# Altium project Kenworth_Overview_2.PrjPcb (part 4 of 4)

## Sheet Rectifier.SchDoc: <Document>
size Letter; Engineer: <Engineer>; Organization: UPEL; Address1: USU Power Electronics Lab; Address2: USTAR Building 620, RM 118; Address3: 1600 N 620 E; Address4: North Logan, UT 84341; DocumentNumber: 13; Revision: v1; SheetNumber: 13; SheetTotal: 16
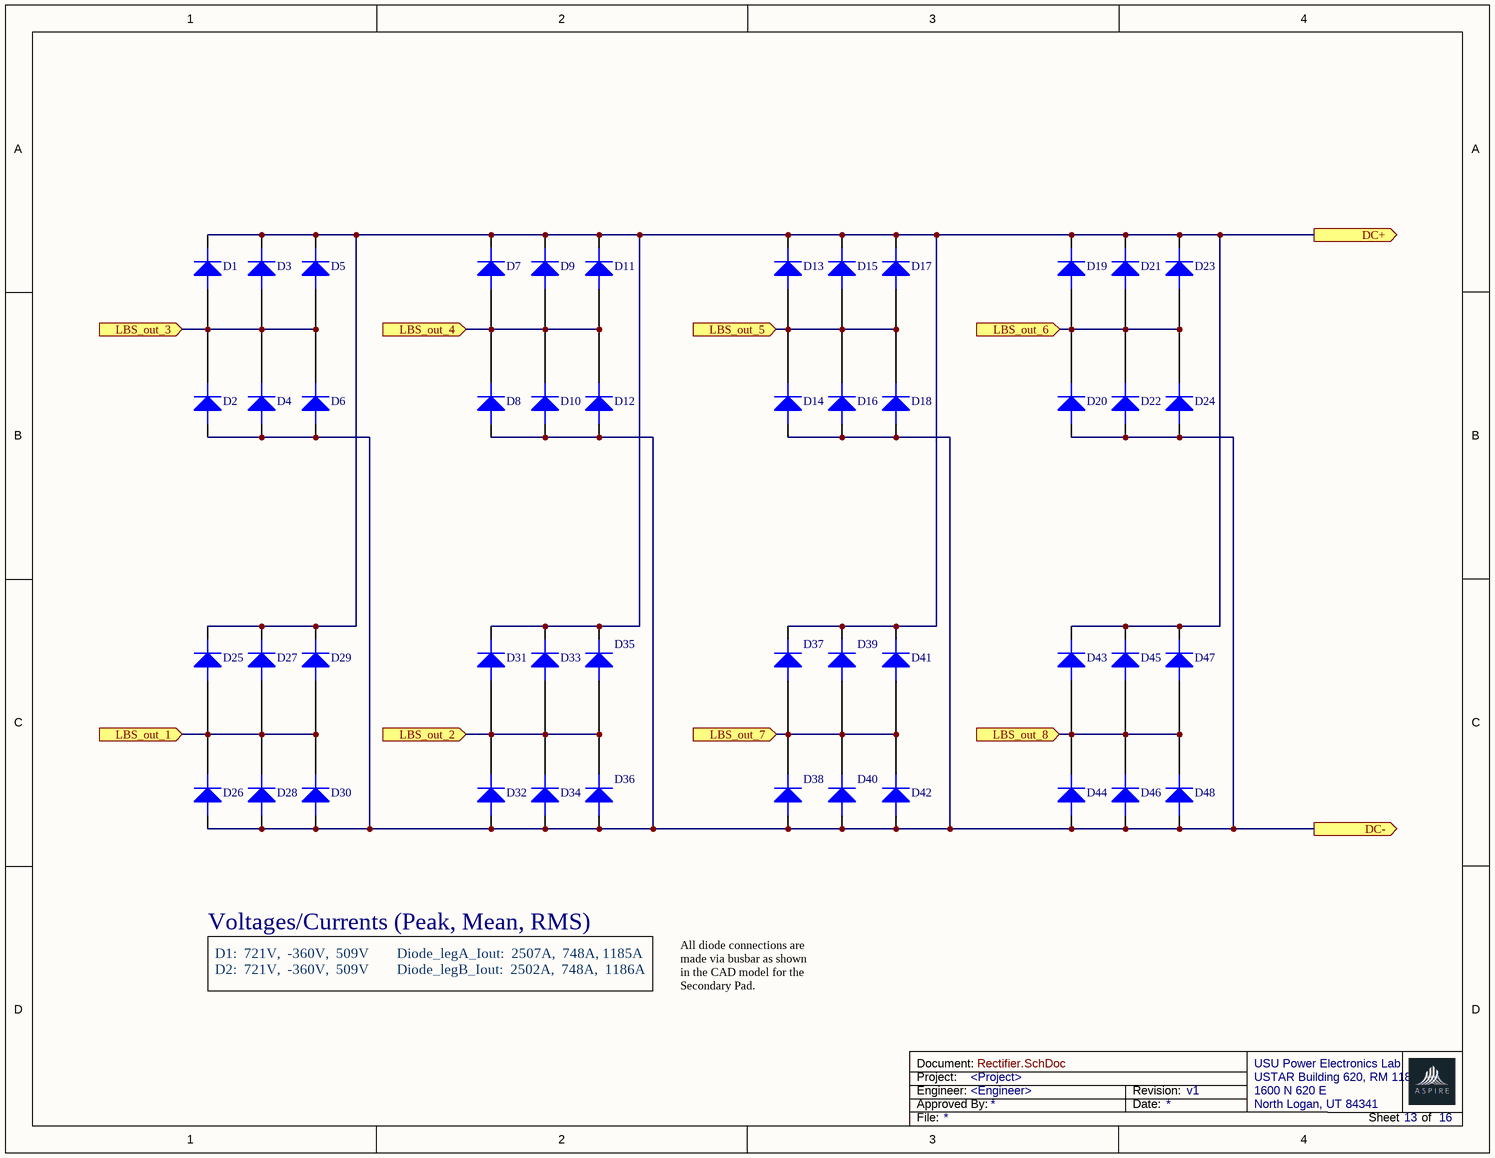
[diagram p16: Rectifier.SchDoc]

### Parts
(Parts that share a designator on the sheet are numbered #1, #2 ... from top to bottom, then left to right.)
D1#2  Diode  (value not drawn)
D2#2  Diode  (value not drawn)
D3#2  Diode  (value not drawn)
D4#2  Diode  (value not drawn)
D5#2  Diode  (value not drawn)
D6#2  Diode  (value not drawn)
D7  Diode  (value not drawn)
D8  Diode  (value not drawn)
D9  Diode  (value not drawn)
D10  Diode  (value not drawn)
D11  Diode  (value not drawn)
D12  Diode  (value not drawn)
D13  Diode  (value not drawn)
D14  Diode  (value not drawn)
D15  Diode  (value not drawn)
D16  Diode  (value not drawn)
D17  Diode  (value not drawn)
D18  Diode  (value not drawn)
D19  Diode  (value not drawn)
D20  Diode  (value not drawn)
D21  Diode  (value not drawn)
D22  Diode  (value not drawn)
D23  Diode  (value not drawn)
D24  Diode  (value not drawn)
D25  Diode  (value not drawn)
D26  Diode  (value not drawn)
D27  Diode  (value not drawn)
D28  Diode  (value not drawn)
D29  Diode  (value not drawn)
D30  Diode  (value not drawn)
D31  Diode  (value not drawn)
D32  Diode  (value not drawn)
D33  Diode  (value not drawn)
D34  Diode  (value not drawn)
D35  Diode  (value not drawn)
D36  Diode  (value not drawn)
D37  Diode  (value not drawn)
D38  Diode  (value not drawn)
D39  Diode  (value not drawn)
D40  Diode  (value not drawn)
D41  Diode  (value not drawn)
D42  Diode  (value not drawn)
D43  Diode  (value not drawn)
D44  Diode  (value not drawn)
D45  Diode  (value not drawn)
D46  Diode  (value not drawn)
D47  Diode  (value not drawn)
D48  Diode  (value not drawn)

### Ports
DC+ (out), DC- (out), LBS_out_1 (in), LBS_out_2 (in), LBS_out_3 (in), LBS_out_4 (in), LBS_out_5 (in), LBS_out_6 (in), LBS_out_7 (in), LBS_out_8 (in)

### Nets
DC+: D1#2.1 D3#2.1 D5#2.1 D7.1 D9.1 D11.1 D13.1 D15.1 D17.1 D19.1 D21.1 D23.1 D25.1 D27.1 D29.1 D31.1 D33.1 D35.1 D37.1 D39.1 D41.1 D43.1 D45.1 D47.1 ; port DC+
DC-: D2#2.0 D4#2.0 D6#2.0 D8.0 D10.0 D12.0 D14.0 D16.0 D18.0 D20.0 D22.0 D24.0 D26.0 D28.0 D30.0 D32.0 D34.0 D36.0 D38.0 D40.0 D42.0 D44.0 D46.0 D48.0 ; port DC-
LBS_out_1: D25.0 D26.1 D27.0 D28.1 D29.0 D30.1 ; port LBS_out_1
LBS_out_2: D31.0 D32.1 D33.0 D34.1 D35.0 D36.1 ; port LBS_out_2
LBS_out_3: D1#2.0 D2#2.1 D3#2.0 D4#2.1 D5#2.0 D6#2.1 ; port LBS_out_3
LBS_out_4: D7.0 D8.1 D9.0 D10.1 D11.0 D12.1 ; port LBS_out_4
LBS_out_5: D13.0 D14.1 D15.0 D16.1 D17.0 D18.1 ; port LBS_out_5
LBS_out_6: D19.0 D20.1 D21.0 D22.1 D23.0 D24.1 ; port LBS_out_6
LBS_out_7: D37.0 D38.1 D39.0 D40.1 D41.0 D42.1 ; port LBS_out_7
LBS_out_8: D43.0 D44.1 D45.0 D46.1 D47.0 D48.1 ; port LBS_out_8

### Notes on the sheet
- Voltages/Currents (Peak, Mean, RMS)
- D1:  721V,  -360V,  509V
  D2:  721V,  -360V,  509V
- Diode_legA_Iout:  2507A,  748A, 1185A
  Diode_legB_Iout:  2502A,  748A,  1186A
- All diode connections are made via busbar as shown in the CAD model for the Secondary Pad.

## Sheet Underground_Assembly.SchDoc: <Document>
size Letter; Engineer: <Engineer>; Organization: UPEL; Address1: USU Power Electronics Lab; Address2: USTAR Building 620, RM 118; Address3: 1600 N 620 E; Address4: North Logan, UT 84341; DocumentNumber: 11; Revision: v1; SheetNumber: 11; SheetTotal: 16
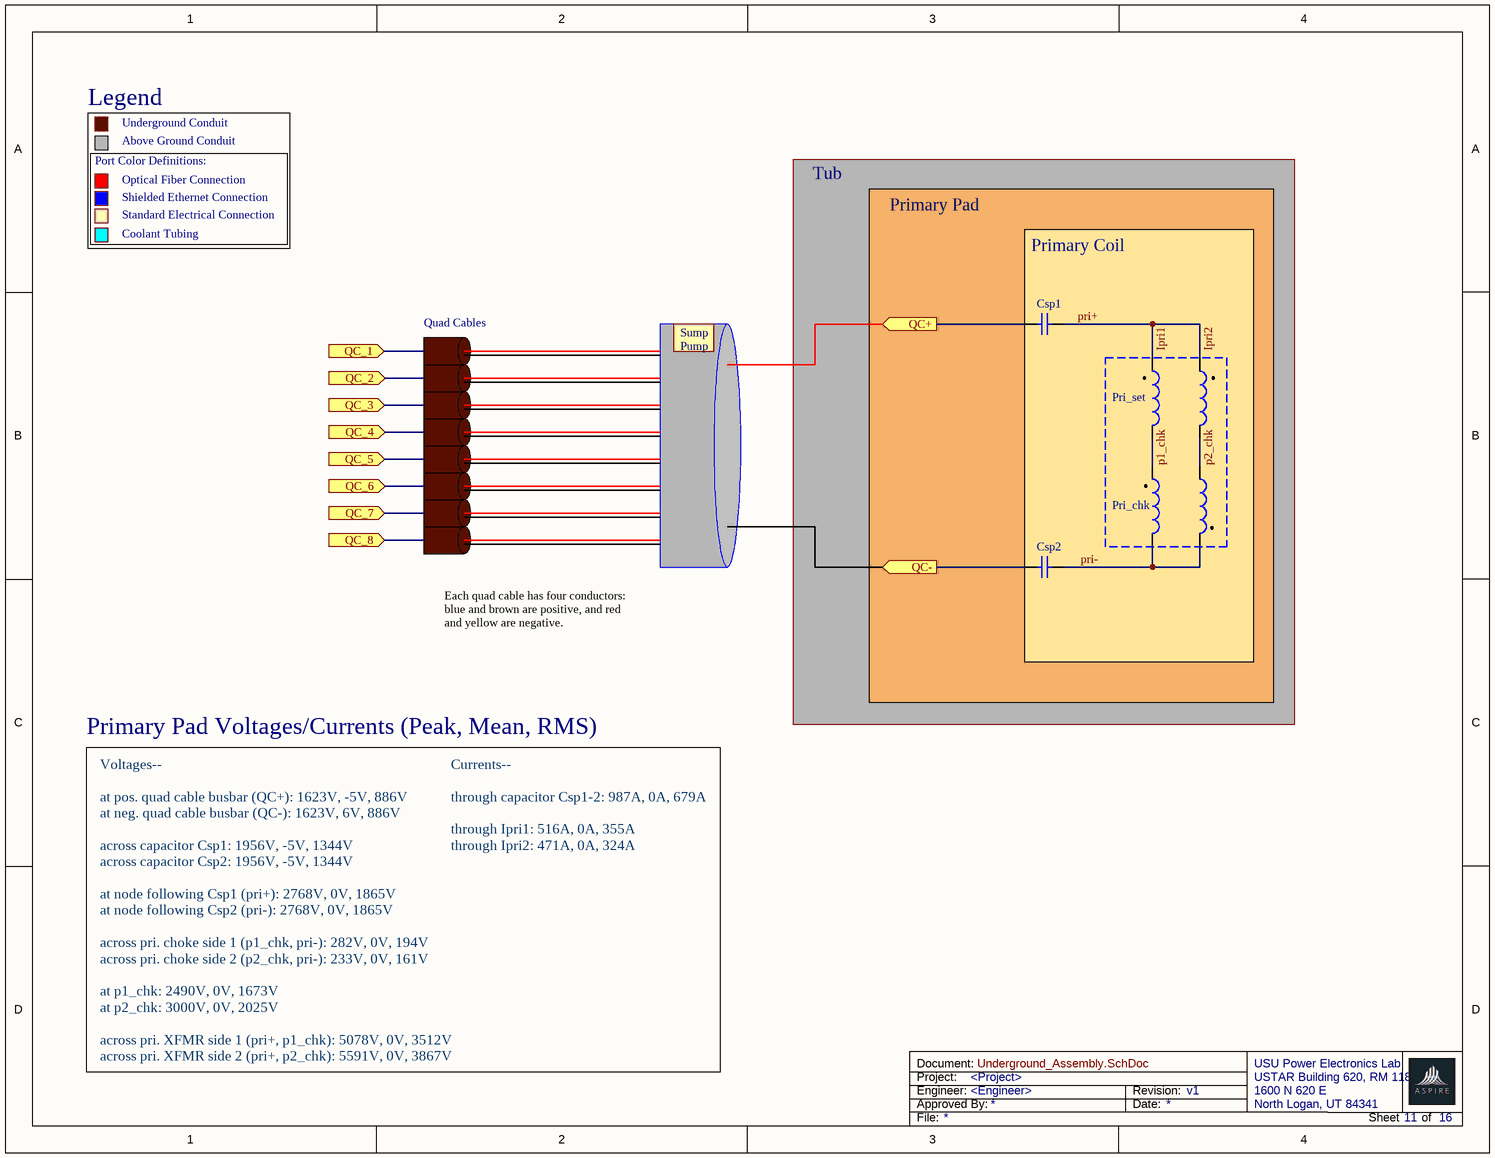
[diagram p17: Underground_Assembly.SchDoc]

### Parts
(Parts that share a designator on the sheet are numbered #1, #2 ... from top to bottom, then left to right.)
Csp1  Capacitor  (value not drawn)
Csp2  Capacitor  (value not drawn)
L?#11  Inductor  (value not drawn)
L?#12  Inductor  (value not drawn)
L?#13  Inductor  (value not drawn)
L?#14  Inductor  (value not drawn)

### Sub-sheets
Designator = File Name (file not in this document): no entries

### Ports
QC+ (in), QC- (in), QC_1 (in), QC_2 (in), QC_3 (in), QC_4 (in), QC_5 (in), QC_6 (in), QC_7 (in), QC_8 (in)

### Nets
Ipri1: Csp1.2 L?#11.2 L?#12.2  [also labelled Ipri2, pri+]
p1_chk: L?#11.1 L?#13.2
p2_chk: L?#12.1 L?#14.2
pri-: Csp2.2 L?#13.1 L?#14.1
QC+: Csp1.1 ; port QC+
QC-: Csp2.1 ; port QC-

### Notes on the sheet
- Legend
- Port Color Definitions:
- Underground Conduit
- Above Ground Conduit
- Optical Fiber Connection
- Shielded Ethernet Connection
- Standard Electrical Connection
- Coolant Tubing
- Tub
- Primary Pad
- Primary Coil
- Quad Cables
- Sump
  Pump
- (near L?#11) Pri_set
- (near L?#13) Pri_chk
- Each quad cable has four conductors: blue and brown are positive, and red and yellow are negative.
- Primary Pad Voltages/Currents (Peak, Mean, RMS)
- Currents--
  through capacitor Csp1-2: 987A, 0A, 679A
  through Ipri1: 516A, 0A, 355A
  through Ipri2: 471A, 0A, 324A
- Voltages--
  at pos. quad cable busbar (QC+): 1623V, -5V, 886V
  at neg. quad cable busbar (QC-): 1623V, 6V, 886V
  across capacitor Csp1: 1956V, -5V, 1344V
  across capacitor Csp2: 1956V, -5V, 1344V
  at node following Csp1 (pri+): 2768V, 0V, 1865V
  at node following Csp2 (pri-): 2768V, 0V, 1865V
  across pri. choke side 1 (p1_chk, pri-): 282V, 0V, 194V
  across pri. choke side 2 (p2_chk, pri-): 233V, 0V, 161V
  at p1_chk: 2490V, 0V, 1673V
  at p2_chk: 3000V, 0V, 2025V
  across pri. XFMR side 1 (pri+, p1_chk): 5078V, 0V, 3512V
  across pri. XFMR side 2 (pri+, p2_chk): 5591V, 0V, 3867V

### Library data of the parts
Csp1 = Capacitor: SimulationGenericComponent: True; Value: 1.66uF
Csp2 = Capacitor: SimulationGenericComponent: True; Value: 2.22uF
L?#11-L?#14 = Inductor: SimulationGenericComponent: True; Value: 1u

## Sheet Secondary_Pad_Auxiliary_Wiring_Overview.SchDoc
size A
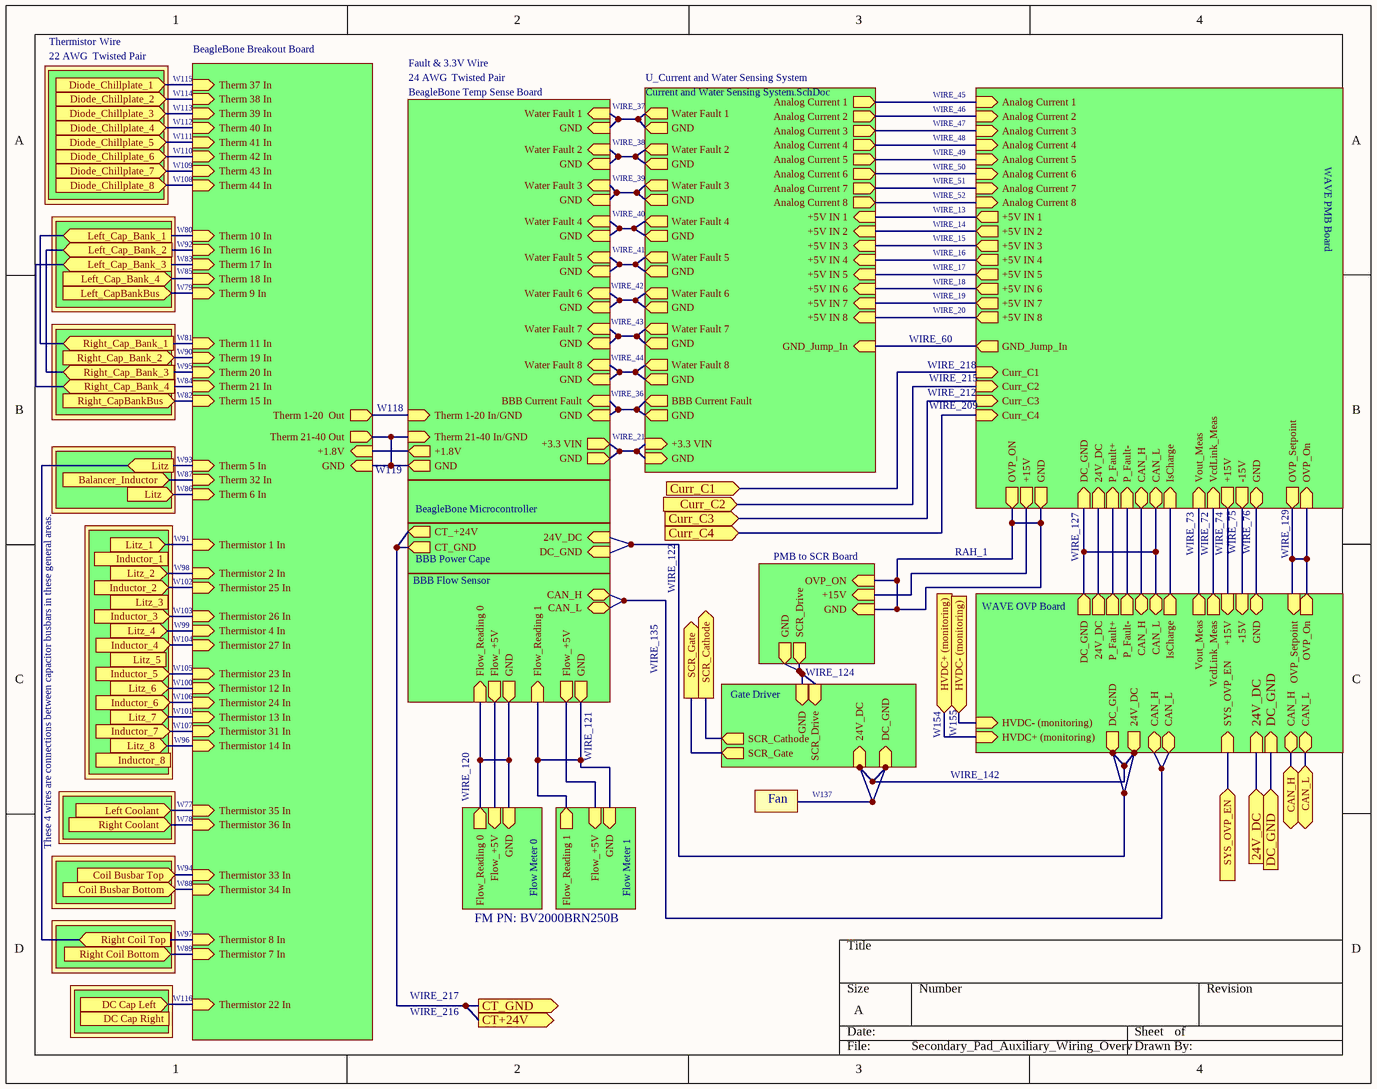
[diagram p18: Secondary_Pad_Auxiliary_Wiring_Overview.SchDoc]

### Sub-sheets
BBB Flow Sensor = File Name (file not in this document): CAN_H (bidir), CAN_L (bidir), Flow_+5V (out), GND (out), Flow_Reading 1 (in), Flow_Reading 0 (in), Flow_+5V (out), GND (out)
BBB Power Cape = File Name (file not in this document): DC_GND (in), 24V_DC (in), CT_GND (out), CT_+24V (out)
BeagleBone Breakout Board = BeagleBone Breakout Board (file not in this document): Therm 37 In (in), Therm 38 In (in), Therm 39 In (in), Therm 40 In (in), Therm 41 In (in), Therm 42 In (in), Therm 43 In (in), Therm 44 In (in), Therm 10 In (in), Therm 16 In (in), Therm 17 In (in), Therm 18 In (in), Therm 9 In (in), Therm 20 In (in), Therm 19 In (in), Therm 11 In (in), Therm 21 In (in), Therm 15 In (in), Therm 5 In (in), Therm 32 In (in), Therm 6 In (in), Thermistor 1 In (in), Thermistor 24 In (in), Thermistor 2 In (in), Thermistor 25 In (in), Thermistor 26 In (in), Thermistor 4 In (in), Thermistor 12 In (in), Thermistor 31 In (in), Thermistor 14 In (in), Thermistor 13 In (in), Therm 1-20  Out (out), Therm 21-40 Out (out), Thermistor 27 In (in), Thermistor 35 In (in), Thermistor 36 In (in), Thermistor 8 In (in), Thermistor 7 In (in), Thermistor 22 In (in), Thermistor 23 In (in), Thermistor 33 In (in), Thermistor 34 In (in), +1.8V (in), GND (in)
BeagleBone Microcontroller = File Name (file not in this document): no entries
BeagleBone Temp Sense Board = File Name (file not in this document): Water Fault 1 (in), Water Fault 5 (in), Water Fault 2 (in), Water Fault 4 (in), Water Fault 6 (in), Water Fault 7 (in), BBB Current Fault (in), Water Fault 8 (in), Therm 1-20 In/GND (in), Therm 21-40 In/GND (in), Water Fault 3 (in), GND (in), GND (in), GND (in), GND (in), GND (in), GND (in), GND (in), GND (in), GND (in), +1.8V (out), GND (out), +3.3 VIN (out), GND (out)
Coil 4 = File Name (file not in this document): no entries
Coil 4 = File Name (file not in this document): no entries
Coil 4 = File Name (file not in this document): no entries
Coil 4 = File Name (file not in this document): no entries
Coil 4 = File Name (file not in this document): no entries
Coil 4 = File Name (file not in this document): no entries
Coil 4 = File Name (file not in this document): no entries
Coil 4 = File Name (file not in this document): no entries
Coil 4 = File Name (file not in this document): no entries
Designator = WAVE OVP Board (file not in this document): Vout_Meas (out), VcdLink_Meas (out), GND (bidir), +15V (in), OVP_On (out), OVP_Setpoint (in), -15V (in), IsCharge (out), P_Fault- (out), P_Fault+ (out), 24V_DC (out), DC_GND (out), CAN_H (bidir), CAN_L (bidir), 24V_DC (in), DC_GND (in), SYS_OVP_EN (in), CAN_H (bidir), CAN_L (bidir), 24V_DC (out), DC_GND (out), CAN_H (bidir), CAN_L (bidir), HVDC- (monitoring) (in), HVDC+ (monitoring) (in)
Flow Meter 0 = File Name (file not in this document): Flow_Reading 0 (out), Flow_+5V (in), GND (in)
Flow Meter 1 = File Name (file not in this document): Flow_Reading 1 (out), Flow_+5V (in), GND (in)
Gate Driver = File Name (file not in this document): SCR_Drive (in), GND (in), SCR_Cathode (out), SCR_Gate (out), DC_GND (in), 24V_DC (in)
PMB to SCR Board = File Name (file not in this document): GND (in), OVP_ON (in), SCR_Drive (out), GND (out), +15V (in)
U_Current and Water Sensing System = Current and Water Sensing System.SchDoc (file not in this document): Water Fault 1 (out), Water Fault 2 (out), Water Fault 3 (out), Water Fault 4 (out), Water Fault 5 (out), Water Fault 6 (out), Water Fault 7 (out), Water Fault 8 (out), BBB Current Fault (out), Analog Current 1 (out), Analog Current 2 (out), Analog Current 3 (out), Analog Current 4 (out), Analog Current 5 (out), Analog Current 6 (out), Analog Current 7 (out), Analog Current 8 (out), +5V IN 1 (in), +5V IN 2 (in), +5V IN 3 (in), +5V IN 4 (in), +5V IN 5 (in), +5V IN 6 (in), +5V IN 7 (in), +5V IN 8 (in), GND (out), GND (out), GND (out), GND (out), GND (out), GND (out), GND (out), GND (out), GND (out), GND_Jump_In (in), +3.3 VIN (in), GND (in)
WAVE PMB Board = File Name (file not in this document): +5V IN 1 (out), +5V IN 2 (out), +5V IN 3 (out), +5V IN 4 (out), +5V IN 5 (out), +5V IN 6 (out), +5V IN 7 (out), +5V IN 8 (out), Vout_Meas (in), VcdLink_Meas (in), GND (bidir), -15V (out), +15V (out), IsCharge (in), P_Fault- (in), P_Fault+ (in), Analog Current 1 (in), Analog Current 2 (in), Analog Current 3 (in), Analog Current 4 (in), Analog Current 5 (in), Analog Current 6 (in), Analog Current 7 (in), Analog Current 8 (in), GND_Jump_In (out), 24V_DC (in), DC_GND (in), OVP_Setpoint (out), OVP_On (in), Curr_C2 (in), Curr_C1 (in), Curr_C4 (in), Curr_C3 (in), CAN_H (bidir), CAN_L (bidir), +15V (out), OVP_ON (out), GND (out)

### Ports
24V_DC (in), Balancer_Inductor (in), CAN_H (bidir), CAN_L (bidir), Coil Busbar Bottom (in), Coil Busbar Top (in), CT+24V (out), CT_GND (out), Curr_C1 (in), Curr_C2 (in), Curr_C3 (in), Curr_C4 (in), DC Cap Left (in), DC Cap Right (in), DC_GND (in), Diode_Chillplate_1 (in), Diode_Chillplate_2 (in), Diode_Chillplate_3 (in), Diode_Chillplate_4 (in), Diode_Chillplate_5 (in), Diode_Chillplate_6 (in), Diode_Chillplate_7 (in), Diode_Chillplate_8 (in), HVDC+ (monitoring) (in), HVDC- (monitoring) (in), Inductor_1 (in), Inductor_2 (in), Inductor_3 (in), Inductor_4 (in), Inductor_5 (in), Inductor_6 (in), Inductor_7 (in), Inductor_8 (in), Left Coolant (in), Left_Cap_Bank_1 (in), Left_Cap_Bank_2 (in), Left_Cap_Bank_3 (in), Left_Cap_Bank_4 (in), Left_CapBankBus (in), Litz (in), Litz_1 (in), Litz_2 (in), Litz_3 (in), Litz_4 (in), Litz_5 (in), Litz_6 (in), Litz_7 (in), Litz_8 (in), Right Coil Bottom (in), Right Coil Top (in), Right Coolant (in), Right_Cap_Bank_1 (in), Right_Cap_Bank_2 (in), Right_Cap_Bank_3 (in), Right_Cap_Bank_4 (in), Right_CapBankBus (in), SCR_Cathode (out), SCR_Gate (out), SYS_OVP_EN (in)

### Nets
24V_DC: port 24V_DC, sheet Designator/24V_DC
Balancer_Inductor: port Balancer_Inductor, sheet BeagleBone Breakout Board/Therm 32 In
CAN_H: port CAN_H, sheet Designator/CAN_H
CAN_L: port CAN_L, sheet Designator/CAN_L
Coil Busbar Bottom: port Coil Busbar Bottom, sheet BeagleBone Breakout Board/Thermistor 34 In
Coil Busbar Top: port Coil Busbar Top, sheet BeagleBone Breakout Board/Thermistor 33 In
CT+24V: port CT_GND, port CT+24V, sheet BBB Power Cape/CT_GND, sheet BBB Power Cape/CT_+24V
Curr_C1: port Curr_C1, sheet WAVE PMB Board/Curr_C1
Curr_C2: port Curr_C2, sheet WAVE PMB Board/Curr_C2
Curr_C3: port Curr_C3, sheet WAVE PMB Board/Curr_C3
Curr_C4: port Curr_C4, sheet WAVE PMB Board/Curr_C4
DC Cap Left: port DC Cap Left, sheet BeagleBone Breakout Board/Thermistor 22 In
DC_GND: port DC_GND, sheet Designator/DC_GND
Diode_Chillplate_1: port Diode_Chillplate_1, sheet BeagleBone Breakout Board/Therm 37 In
Diode_Chillplate_2: port Diode_Chillplate_2, sheet BeagleBone Breakout Board/Therm 38 In
Diode_Chillplate_3: port Diode_Chillplate_3, sheet BeagleBone Breakout Board/Therm 39 In
Diode_Chillplate_4: port Diode_Chillplate_4, sheet BeagleBone Breakout Board/Therm 40 In
Diode_Chillplate_5: port Diode_Chillplate_5, sheet BeagleBone Breakout Board/Therm 41 In
Diode_Chillplate_6: port Diode_Chillplate_6, sheet BeagleBone Breakout Board/Therm 42 In
Diode_Chillplate_7: port Diode_Chillplate_7, sheet BeagleBone Breakout Board/Therm 43 In
Diode_Chillplate_8: port Diode_Chillplate_8, sheet BeagleBone Breakout Board/Therm 44 In
HVDC+ (monitoring): port HVDC+ (monitoring), sheet Designator/HVDC+ (monitoring)
HVDC- (monitoring): port HVDC- (monitoring), sheet Designator/HVDC- (monitoring)
Inductor_2: port Inductor_2, sheet BeagleBone Breakout Board/Thermistor 25 In
Inductor_3: port Inductor_3, sheet BeagleBone Breakout Board/Thermistor 26 In
Inductor_4: port Inductor_4, sheet BeagleBone Breakout Board/Thermistor 27 In
Inductor_5: port Inductor_5, sheet BeagleBone Breakout Board/Thermistor 23 In
Inductor_6: port Inductor_6, sheet BeagleBone Breakout Board/Thermistor 24 In
Inductor_7: port Inductor_7, sheet BeagleBone Breakout Board/Thermistor 31 In
Left Coolant: port Left Coolant, sheet BeagleBone Breakout Board/Thermistor 35 In
Left_Cap_Bank_1: port Right_Cap_Bank_1, port Left_Cap_Bank_1, sheet BeagleBone Breakout Board/Therm 10 In, sheet BeagleBone Breakout Board/Therm 11 In
Left_Cap_Bank_2: port Right_Cap_Bank_3, port Left_Cap_Bank_2, sheet BeagleBone Breakout Board/Therm 16 In, sheet BeagleBone Breakout Board/Therm 20 In
Left_Cap_Bank_3: port Right_Cap_Bank_4, port Left_Cap_Bank_3, sheet BeagleBone Breakout Board/Therm 17 In, sheet BeagleBone Breakout Board/Therm 21 In
Left_Cap_Bank_4: port Left_Cap_Bank_4, sheet BeagleBone Breakout Board/Therm 18 In
Left_CapBankBus: port Left_CapBankBus, sheet BeagleBone Breakout Board/Therm 9 In
Litz: port Litz, port Right Coil Top, sheet BeagleBone Breakout Board/Therm 5 In, sheet BeagleBone Breakout Board/Therm 6 In, sheet BeagleBone Breakout Board/Thermistor 8 In
Litz_1: port Litz_1, sheet BeagleBone Breakout Board/Thermistor 1 In
Litz_2: port Litz_2, sheet BeagleBone Breakout Board/Thermistor 2 In
Litz_4: port Litz_4, sheet BeagleBone Breakout Board/Thermistor 4 In
Litz_6: port Litz_6, sheet BeagleBone Breakout Board/Thermistor 12 In
Litz_7: port Litz_7, sheet BeagleBone Breakout Board/Thermistor 13 In
Litz_8: port Litz_8, sheet BeagleBone Breakout Board/Thermistor 14 In
Right Coil Bottom: port Right Coil Bottom, sheet BeagleBone Breakout Board/Thermistor 7 In
Right Coolant: port Right Coolant, sheet BeagleBone Breakout Board/Thermistor 36 In
Right_Cap_Bank_2: port Right_Cap_Bank_2, sheet BeagleBone Breakout Board/Therm 19 In
Right_CapBankBus: port Right_CapBankBus, sheet BeagleBone Breakout Board/Therm 15 In
SCR_Cathode: port SCR_Cathode, sheet Gate Driver/SCR_Cathode
SCR_Gate: port SCR_Gate, sheet Gate Driver/SCR_Gate
SYS_OVP_EN: port SYS_OVP_EN, sheet Designator/SYS_OVP_EN
(unnamed): sheet BBB Power Cape/24V_DC, sheet Gate Driver/DC_GND, sheet Gate Driver/24V_DC, sheet Designator/24V_DC, sheet Designator/DC_GND
(unnamed): sheet BBB Flow Sensor/CAN_H, sheet BBB Flow Sensor/CAN_L, sheet Designator/CAN_H, sheet Designator/CAN_L  [a separate net that carries the same name]
(unnamed): sheet BBB Flow Sensor/Flow_+5V, sheet Flow Meter 0/Flow_+5V  [a separate net that carries the same name]
(unnamed): sheet BBB Flow Sensor/GND, sheet BBB Flow Sensor/Flow_Reading 0, sheet Flow Meter 0/Flow_Reading 0, sheet Flow Meter 0/GND  [a separate net that carries the same name]
(unnamed): sheet BBB Flow Sensor/Flow_Reading 1, sheet BBB Flow Sensor/GND, sheet Flow Meter 1/Flow_Reading 1, sheet Flow Meter 1/GND  [a separate net that carries the same name]
(unnamed): sheet BBB Flow Sensor/Flow_+5V, sheet Flow Meter 1/Flow_+5V  [a separate net that carries the same name]
(unnamed): sheet BeagleBone Temp Sense Board/Water Fault 1, sheet BeagleBone Temp Sense Board/GND, sheet U_Current and Water Sensing System/Water Fault 1, sheet U_Current and Water Sensing System/GND  [a separate net that carries the same name]
(unnamed): sheet BeagleBone Temp Sense Board/Water Fault 5, sheet BeagleBone Temp Sense Board/GND, sheet U_Current and Water Sensing System/Water Fault 5, sheet U_Current and Water Sensing System/GND  [a separate net that carries the same name]
(unnamed): sheet BeagleBone Temp Sense Board/Water Fault 2, sheet BeagleBone Temp Sense Board/GND, sheet U_Current and Water Sensing System/Water Fault 2, sheet U_Current and Water Sensing System/GND  [a separate net that carries the same name]
(unnamed): sheet BeagleBone Temp Sense Board/Water Fault 4, sheet BeagleBone Temp Sense Board/GND, sheet U_Current and Water Sensing System/Water Fault 4, sheet U_Current and Water Sensing System/GND  [a separate net that carries the same name]
(unnamed): sheet BeagleBone Temp Sense Board/Water Fault 6, sheet BeagleBone Temp Sense Board/GND, sheet U_Current and Water Sensing System/Water Fault 6, sheet U_Current and Water Sensing System/GND  [a separate net that carries the same name]
(unnamed): sheet BeagleBone Temp Sense Board/Water Fault 7, sheet BeagleBone Temp Sense Board/GND, sheet U_Current and Water Sensing System/Water Fault 7, sheet U_Current and Water Sensing System/GND  [a separate net that carries the same name]
(unnamed): sheet BeagleBone Temp Sense Board/BBB Current Fault, sheet BeagleBone Temp Sense Board/GND, sheet U_Current and Water Sensing System/BBB Current Fault, sheet U_Current and Water Sensing System/GND  [a separate net that carries the same name]
(unnamed): sheet BeagleBone Temp Sense Board/Water Fault 8, sheet BeagleBone Temp Sense Board/GND, sheet U_Current and Water Sensing System/Water Fault 8, sheet U_Current and Water Sensing System/GND  [a separate net that carries the same name]
(unnamed): sheet BeagleBone Temp Sense Board/Therm 1-20 In/GND, sheet BeagleBone Breakout Board/Therm 1-20  Out  [a separate net that carries the same name]
(unnamed): sheet BeagleBone Temp Sense Board/Therm 21-40 In/GND, sheet BeagleBone Temp Sense Board/GND, sheet BeagleBone Breakout Board/Therm 21-40 Out, sheet BeagleBone Breakout Board/GND  [a separate net that carries the same name]
(unnamed): sheet BeagleBone Temp Sense Board/Water Fault 3, sheet BeagleBone Temp Sense Board/GND, sheet U_Current and Water Sensing System/Water Fault 3, sheet U_Current and Water Sensing System/GND  [a separate net that carries the same name]
(unnamed): sheet BeagleBone Temp Sense Board/+1.8V, sheet BeagleBone Breakout Board/+1.8V  [a separate net that carries the same name]
(unnamed): sheet BeagleBone Temp Sense Board/+3.3 VIN, sheet BeagleBone Temp Sense Board/GND, sheet U_Current and Water Sensing System/+3.3 VIN, sheet U_Current and Water Sensing System/GND  [a separate net that carries the same name]
(unnamed): sheet U_Current and Water Sensing System/Analog Current 1, sheet WAVE PMB Board/Analog Current 1  [a separate net that carries the same name]
(unnamed): sheet U_Current and Water Sensing System/Analog Current 2, sheet WAVE PMB Board/Analog Current 2  [a separate net that carries the same name]
(unnamed): sheet U_Current and Water Sensing System/Analog Current 3, sheet WAVE PMB Board/Analog Current 3  [a separate net that carries the same name]
(unnamed): sheet U_Current and Water Sensing System/Analog Current 4, sheet WAVE PMB Board/Analog Current 4  [a separate net that carries the same name]
(unnamed): sheet U_Current and Water Sensing System/Analog Current 5, sheet WAVE PMB Board/Analog Current 5  [a separate net that carries the same name]
(unnamed): sheet U_Current and Water Sensing System/Analog Current 6, sheet WAVE PMB Board/Analog Current 6  [a separate net that carries the same name]
(unnamed): sheet U_Current and Water Sensing System/Analog Current 7, sheet WAVE PMB Board/Analog Current 7  [a separate net that carries the same name]
(unnamed): sheet U_Current and Water Sensing System/Analog Current 8, sheet WAVE PMB Board/Analog Current 8  [a separate net that carries the same name]
(unnamed): sheet U_Current and Water Sensing System/+5V IN 1, sheet WAVE PMB Board/+5V IN 1  [a separate net that carries the same name]
(unnamed): sheet U_Current and Water Sensing System/+5V IN 2, sheet WAVE PMB Board/+5V IN 2  [a separate net that carries the same name]
(unnamed): sheet U_Current and Water Sensing System/+5V IN 3, sheet WAVE PMB Board/+5V IN 3  [a separate net that carries the same name]
(unnamed): sheet U_Current and Water Sensing System/+5V IN 4, sheet WAVE PMB Board/+5V IN 4  [a separate net that carries the same name]
(unnamed): sheet U_Current and Water Sensing System/+5V IN 5, sheet WAVE PMB Board/+5V IN 5  [a separate net that carries the same name]
(unnamed): sheet U_Current and Water Sensing System/+5V IN 6, sheet WAVE PMB Board/+5V IN 6  [a separate net that carries the same name]
(unnamed): sheet U_Current and Water Sensing System/+5V IN 7, sheet WAVE PMB Board/+5V IN 7  [a separate net that carries the same name]
(unnamed): sheet U_Current and Water Sensing System/+5V IN 8, sheet WAVE PMB Board/+5V IN 8  [a separate net that carries the same name]
(unnamed): sheet U_Current and Water Sensing System/GND_Jump_In, sheet WAVE PMB Board/GND_Jump_In  [a separate net that carries the same name]
(unnamed): sheet WAVE PMB Board/Vout_Meas, sheet Designator/Vout_Meas  [a separate net that carries the same name]
(unnamed): sheet WAVE PMB Board/VcdLink_Meas, sheet Designator/VcdLink_Meas  [a separate net that carries the same name]
(unnamed): sheet WAVE PMB Board/GND, sheet Designator/GND  [a separate net that carries the same name]
(unnamed): sheet WAVE PMB Board/-15V, sheet Designator/-15V  [a separate net that carries the same name]
(unnamed): sheet WAVE PMB Board/+15V, sheet Designator/+15V  [a separate net that carries the same name]
(unnamed): sheet WAVE PMB Board/IsCharge, sheet Designator/IsCharge  [a separate net that carries the same name]
(unnamed): sheet WAVE PMB Board/P_Fault-, sheet Designator/P_Fault-  [a separate net that carries the same name]
(unnamed): sheet WAVE PMB Board/P_Fault+, sheet Designator/P_Fault+  [a separate net that carries the same name]
(unnamed): sheet WAVE PMB Board/24V_DC, sheet Designator/24V_DC  [a separate net that carries the same name]
(unnamed): sheet WAVE PMB Board/DC_GND, sheet WAVE PMB Board/CAN_L, sheet Designator/DC_GND, sheet Designator/CAN_L  [a separate net that carries the same name]
(unnamed): sheet WAVE PMB Board/OVP_Setpoint, sheet WAVE PMB Board/OVP_On, sheet Designator/OVP_On  [a separate net that carries the same name]
(unnamed): sheet WAVE PMB Board/CAN_H, sheet Designator/CAN_H  [a separate net that carries the same name]
(unnamed): sheet WAVE PMB Board/+15V, sheet PMB to SCR Board/+15V  [a separate net that carries the same name]
(unnamed): sheet WAVE PMB Board/OVP_ON, sheet WAVE PMB Board/GND, sheet PMB to SCR Board/OVP_ON  [a separate net that carries the same name]
(unnamed): sheet PMB to SCR Board/SCR_Drive, sheet PMB to SCR Board/GND, sheet Gate Driver/SCR_Drive, sheet Gate Driver/GND  [a separate net that carries the same name]

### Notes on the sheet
- 22 AWG
- Thermistor
- Twisted Pair
- Wire
- W115
- W114
- W113
- 24 AWG
- Fault & 3.3V Wire
- WIRE_37
- WIRE_45
- W112
- W111
- W110
- W109
- WIRE_38
- WIRE_39
- WIRE_46
- WIRE_47
- WIRE_48
- WIRE_49
- WIRE_50
- W108
- W80
- W92
- WIRE_40
- WIRE_41
- WIRE_13
- WIRE_14
- WIRE_15
- WIRE_51
- WIRE_52
- W83
- W85
- W79
- WIRE_42
- WIRE_43
- WIRE_16
- WIRE_17
- WIRE_18
- WIRE_20
- WIRE_19
- W81
- W90
- W95
- W84
- W82
- WIRE_44
- WIRE_36
- WIRE_60
- WIRE_218
- WIRE_212
- WIRE_215
- W93
- W118
- WIRE_21
- WIRE_209
- W91
- W87
- W86
- W119
- W102
- W98
- WIRE_122
- RAH_1
- WIRE_127
- WIRE_73
- WIRE_72
- WIRE_74
- WIRE_75
- WIRE_76
- WIRE_129
- W103
- W104
- W105
- W100
- W99
- WIRE_135
- WIRE_124
- W106
- W101
- W107
- W96
- W154
- W155
- W77
- W78
- WIRE_120
- WIRE_121
- Fan
- W137
- WIRE_142
- These 4 wires are connections between capacitor busbars in these general areas.
- W94
- W88
- W97
- W89
- FM PN: BV2000BRN250B
- W116
- WIRE_217
- WIRE_216

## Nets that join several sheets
Phase_A': Special_Equipment_Cabinet_Overview (F68.2), Shunt_Filter (J2.0)
Phase_B': Special_Equipment_Cabinet_Overview (F70.2), Shunt_Filter (J1.0)
Phase_C': Special_Equipment_Cabinet_Overview (F72.2), Shunt_Filter (J3.0)
120 V: Special_Equipment_Cabinet_Overview (T1.3), Auxiliary_Circuit (J19.0)
DC+: Filter (20 pins), Rectifier (24 pins)
DC-: Filter (20 pins), Rectifier (24 pins)
HVDC+: Vehicle_Charger_Hierarchal (SCR.2 SCR.3), Filter (5 pins)
HVDC-: Vehicle_Charger_Hierarchal (7 pins), Filter (C?#2.2 C?#23.1 C?#24.2 R2.1)
Inductors_OUT: Shunt_Filter (J4.0), Special Equipment Cabinet/Shunt Filter/U_RLC (J14_Special_Equipment_Cabinet_Shunt_Filter_U_RLC#1.0)
Inductors_OUT: Shunt_Filter (J4.0), Special Equipment Cabinet/Shunt Filter/U_RLC (J14_Special_Equipment_Cabinet_Shunt_Filter_U_RLC#2.0)
Inductors_OUT: Shunt_Filter (J4.0), Special Equipment Cabinet/Shunt Filter/U_RLC (J14_Special_Equipment_Cabinet_Shunt_Filter_U_RLC#3.0)
LBS_out_1: Vehicle_Charger_Hierarchal (Lbr1.2), Rectifier (6 pins)
LBS_out_2: Vehicle_Charger_Hierarchal (Lbr2.2), Rectifier (6 pins)
LBS_out_3: Vehicle_Charger_Hierarchal (Lbr3.2), Rectifier (6 pins)
LBS_out_4: Vehicle_Charger_Hierarchal (Lbr4.2), Rectifier (6 pins)
LBS_out_5: Vehicle_Charger_Hierarchal (Lbr5.2), Rectifier (6 pins)
LBS_out_6: Vehicle_Charger_Hierarchal (Lbr6.2), Rectifier (6 pins)
LBS_out_7: Vehicle_Charger_Hierarchal (Lbr7.2), Rectifier (6 pins)
LBS_out_8: Vehicle_Charger_Hierarchal (Lbr8.2), Rectifier (6 pins)
N: Fuse_Block (16 pins), Unfolder (5 pins)
N: Special_Equipment_Cabinet_Overview (T1.4), Auxiliary_Circuit (J19.0)
N: Special_Equipment_Cabinet_Overview (J17.1), Shunt_Filter (J4.0)
O: Full_Module (K?#2.4), U_T-Type_Board (C9_U_T-Type_Board#1.1 C11_U_T-Type_Board#1.2 Q17_U_T-Type_Board#1.4 Q21_U_T-Type_Board#1.4)
O: Full_Module (K?#5.4), U_T-Type_Board (C9_U_T-Type_Board#2.1 C11_U_T-Type_Board#2.2 Q17_U_T-Type_Board#2.4 Q21_U_T-Type_Board#2.4)
O: Fuse_Block (16 pins), Unfolder (C1.2 C2.1)
P: Fuse_Block (16 pins), Unfolder (5 pins)
Phase_A_F5_OUT: Shunt_Filter (F14.1), Special Equipment Cabinet/Shunt Filter/U_RLC (C5_Special_Equipment_Cabinet_Shunt_Filter_U_RLC#1.2 ROX5SSJ47K_Special_Equipment_Cabinet_Shunt_Filter_U_RLC#1.2)
PP+: Full_Module (C2-1#2.2 L2#2.1), IGBT PCB (6 pins)
PP+: Full_Module (C2-1#1.2 L2#1.1), IGBT PCB (6 pins)
PP-: Full_Module (C2-3#2.1 L?#5.2), IGBT PCB (6 pins)
PP-: Full_Module (C2-3#1.1 L?#2.2), IGBT PCB (6 pins)
Resistors_OUT: Shunt_Filter (J4.0), Special Equipment Cabinet/Shunt Filter/U_RLC (J15_Special_Equipment_Cabinet_Shunt_Filter_U_RLC#1.0)
Resistors_OUT: Shunt_Filter (J4.0), Special Equipment Cabinet/Shunt Filter/U_RLC (J15_Special_Equipment_Cabinet_Shunt_Filter_U_RLC#2.0)
Resistors_OUT: Shunt_Filter (J4.0), Special Equipment Cabinet/Shunt Filter/U_RLC (J15_Special_Equipment_Cabinet_Shunt_Filter_U_RLC#3.0)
